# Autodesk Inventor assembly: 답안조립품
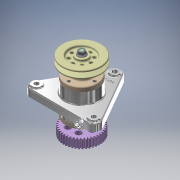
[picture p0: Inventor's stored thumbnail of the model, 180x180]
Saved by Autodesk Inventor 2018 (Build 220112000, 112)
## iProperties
Created: 2023-04
Part Number: 답안조립품
Material: 일반
Document SubType Name: Assembly
Designer: 강의실04
Author: 강의실04
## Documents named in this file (11)
- C:\Users\kimgi\Desktop\730407V1015\답안조립품.iam
- C:\Users\kimgi\Desktop\730407V1015\본체.ipt
- C:\Users\kimgi\Desktop\730407V1015\6각 플랜지 너트 M10.ipt
- C:\Users\kimgi\Desktop\730407V1015\v-벨트풀리.ipt
- C:\Users\kimgi\Desktop\730407V1015\묻힘키 5x5x16.ipt
- C:\Users\kimgi\Desktop\730407V1015\베어링 6204.ipt
- C:\Users\kimgi\Desktop\730407V1015\볼트 M4 x 12.ipt
- C:\Users\kimgi\Desktop\730407V1015\스퍼기어.ipt
- C:\Users\kimgi\Desktop\730407V1015\오일 실 20 32 8.ipt
- C:\Users\kimgi\Desktop\730407V1015\축.ipt
- C:\Users\kimgi\Desktop\730407V1015\커버.ipt
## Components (3 placed, 2 different names)
1. 6각 플랜지 너트 M10:1
2. v-벨트풀리:1
3. 6각 플랜지 너트 M10:2
